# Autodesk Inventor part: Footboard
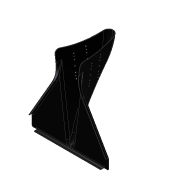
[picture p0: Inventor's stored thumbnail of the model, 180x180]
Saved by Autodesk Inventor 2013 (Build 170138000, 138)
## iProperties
Shininess: 41.0
Length Units: 11269
Angle Units: 11279
Time Units: 11290
Mass Units: 11283
Length Display Precision: 3
Angle Display Precision: 2
Created: 2001-04
Part Number: Footboard
Material: Standard
Document SubType Name: Modellieren
Designer: dl
Density: 1 g/cm^3
Density: 0.0
Volumn: 0.0
Area: 0.0
PropertySet Name: Model Information
Control State: 0
Master: False
Checked Out: False
Author: dl
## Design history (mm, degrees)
sketch "Sketch1"
  geometry: L1 (-28, 0)-(28, 0); L2 (28, 0)-(75, -260); L3 (75, -260)-(-75, -260); L4 (-75, -260)-(-28, 0); L5 (0, 0)-(0, 120.699)
  constraints: 10 end point, 1 equal length, 1 horizontal, 1 midpoint, 1 parallel, 1 perpendicular
  dimensions: "d0" = 150 distance of L2.end L3.end; "d1" = 56 distance of L1.start L1.end; "d2" = 260 vertical distance of L3.end L1.start; "d3" = 47 horizontal distance of L1.start L3.end (derived)
extrude "Extrusion1" new body sketch "Sketch1" distance "d4" = 470; taper "d5" = 0 deg
sketch "Sketch4"
  geometry: L1 (72.458, -470)-(77.542, -470) reference; L2 (150, 0)-(93.206, -455.169) reference; L3 (150, 0)-(0, 0) reference; L4 (0, 0)-(56.794, -455.169) reference; L5 (-146.5, -470)-(296.5, -470); L6 (296.5, -405)-(134.481, -124.375); L7 (-146.5, -405)-(15.519, -124.375); L8 (296.5, -405)-(296.5, -470); L9 (-146.5, -405)-(-146.5, -470); L10 (75, 0)-(75, 36.926)
  constraints: 12 end point, 3 parallel, 2 equal length, 2 point on line, 1 midpoint, 1 perpendicular, 2 other
  dimensions: "d42" = 443 distance of L5.start L5.end; "d43" = 0 distance from line of L5 L1.start; "d44" = 65 distance of L6.start L5.end; "d45" = 30 deg angle of L6 L8; "d46" = 30 deg angle of L7 L9 (= d45); "d47" = 221.5 horizontal distance of L5.end L10.end (derived)
extrude "Extrusion2" join sketch "Sketch4" distance "d48" = 20; taper "d49" = 0 deg
sketch "Sketch6"
  geometry: L1 (324.038, 20)-(357.434, 20); L2 (357.434, 20)-(357.434, 0); L3 (357.434, 0)-(324.038, 0); L4 (324.038, 0)-(324.038, 20); L5 (423.99, 0)-(324.038, 0) reference
  constraints: 8 end point, 2 parallel, 1 horizontal, 1 perpendicular
  dimensions: "d62" = 0 distance from line of L5 L2.end
extrude "Extrusion4" join sketch "Sketch6" distance "d63" = 20; taper "d64" = 0 deg
sketch "Sketch8" dims "d73" = 1000
  geometry: L1 (-260, 0)-(-260, -71.319) reference; L2 (-26.395, 0)-(-260, 0) reference; L3 (-0.319, -2.89)-(-0.319, -19.983); 1 further point
  constraints: 2 end point, 1 perpendicular, 3 other
  dimensions: "d74" = 130 distance from line of L1 point (-130, 480); "d75" = 480 distance from line of L2 point (-130, 480)
extrude "Extrusion6" cut sketch "Sketch8" stored distance "d77" = 300; taper "d78" = 0 deg
sketch "Sketch12"
  geometry: L1 (22, -10)-(-10, -10); L2 (-10, -10)-(-10, 57); L3 (-10, 57)-(22, 57); L4 (22, 57)-(22, -10); L5 (-10, 52.321)-(-10, 0) reference; L6 (0, -10)-(423, -10) reference
  constraints: 8 end point, 2 parallel, 1 horizontal, 1 perpendicular
  dimensions: "d123" = 0 distance from line of L1.end L5; "d124" = 0 distance from line of L6 L1.start; "d125" = 32 distance of L2.end L3.end; "d126" = 67 distance of L3.end L1.start
extrude "Extrusion7" cut sketch "Sketch12" stored distance "d127" = 10; taper "d128" = 0 deg
body "Solid1"
feature "FaceDraft1" dims angle "d17" = 7 deg
sweep "Sweep1" dims "d16" = 0
fillet "Fillet1" dims "d21" = 16.5, "d22" = 32, "d25" = 24, "d26" = 10, "d29" = 23, "d30" = 5, "d34" = 23, "d35" = 7.5, "d38" = 18.5, "d39" = 2.5
fillet "Fillet2" dims "d23" = 32 (= d22), "d24" = 16.5 (= d21), "d27" = 24 (= d25), "d28" = 0, "d31" = 23 (= d29), "d32" = 5, "d36" = 23 (= d34), "d37" = 2.5, "d40" = 18.5 (= d38), "d41" = 7.5
workaxis "Work Axis1"
workaxis "Work Axis2"
workplane "Work Plane1"
sketch "Sketch5"
  geometry: L1 (-118.962, 0)-(-280.981, 0) reference; L2 (-118.962, 0)-(0, 0); L3 (0, 0)-(0, -20); L4 (0, -20)-(-118.962, -20); L5 (-118.962, -20)-(-118.962, 0); L6 (-118.962, -20)-(-280.981, -20) reference
  constraints: 8 end point, 2 parallel, 1 horizontal, 1 perpendicular
  dimensions: "d58" = 0 distance between parallel lines of L6 L4
extrude "Extrusion3" join sketch "Sketch5" stored distance "d56" = 20; taper "d57" = 0 deg
sketch "Sketch7"
  geometry: L1 (-324.038, 20)-(-356.936, 20); L2 (-356.936, 20)-(-356.936, 0); L3 (-356.936, 0)-(-324.038, 0); L4 (-324.038, 0)-(-324.038, 20); L5 (-423.99, 0)-(-324.038, 0) reference
  constraints: 8 end point, 2 parallel, 1 horizontal, 1 perpendicular
  dimensions: "d65" = 0 distance between parallel lines of L5 L3
extrude "Extrusion5" join sketch "Sketch7" distance "d66" = 20; taper "d67" = 0 deg
fillet "Fillet3" dims "d68" = 150
fillet "Fillet4" dims "d69" = 10
fillet "Fillet5" dims "d70" = 10
fillet "Fillet6" dims "d71" = 10
shell "Shell1" dims "d72" = 3
fillet "Fillet7" dims "d79" = 20
sketch "Sketch9"
  geometry: L1 (-36.727, -28.685)-(6.694, -28.685) reference; 3 further points; 1 other entity
  constraints: 1 other
  dimensions: "d80" = 88 distance from line of point (-6.28, 59.315) L1; "d81" = 30 horizontal distance of point (-6.28, 59.315) point (-36.28, -8.366)
hole "Hole1" sketch "Sketch9" diameter "d82" = 6.2; stored, may be unused: countersink angle "d86" = 60 deg, drill point angle "d88" = 118 deg; dims "d83" = 6, "d84" = 4, "d85" = 2, "d87" = 8
pattern_linear "Rectangular Pattern1" dims "d91" = 30
sketch "Sketch10"
  geometry: C1 r 3.1 at (-6.28, 59.315) reference; 1 further point
  dimensions: "d96" = 61 vertical distance of point (-14.28, 120.315) C1.centre; "d97" = 8 horizontal distance of C1.centre point (-14.28, 120.315)
hole "Hole2" sketch "Sketch10" diameter "d98" = 6.2; stored, may be unused: countersink angle "d102" = 60 deg, drill point angle "d104" = 118 deg; dims "d99" = 6, "d100" = 4, "d101" = 2, "d103" = 8
pattern_linear "Rectangular Pattern2" dims "d107" = 30
mirror "Mirror1"
sketch "Sketch11"
  geometry: C1 r 3.1 at (105.72, 120.315) reference; C2 r 3.1 at (75.72, 120.315) reference; C3 r 3.1 at (-14.28, 120.315) reference; C4 r 3.1 at (113.72, 59.315) reference; C5 r 3.1 at (83.72, 59.315) reference; C6 r 3.1 at (-6.28, 59.315) reference; 4 further points
  dimensions: "d108" = 0 vertical distance of C3.centre point (0.72, 120.315); "d109" = 15 distance of C3.centre point (0.72, 120.315); "d110" = 0 vertical distance of C6.centre point (8.72, 59.315); "d111" = 15 distance of C6.centre point (8.72, 59.315) (= d109); "d112" = 0 vertical distance of C1.centre point (90.72, 120.315); "d113" = 0 vertical distance of C4.centre point (98.72, 59.315); "d114" = 15 distance of C2.centre point (90.72, 120.315) (= d109); "d115" = 15 distance of C5.centre point (98.72, 59.315) (= d109)
hole "Hole3" sketch "Sketch11" diameter "d116" = 5; stored, may be unused: countersink angle "d120" = 60 deg, drill point angle "d122" = 118 deg; dims "d117" = 6, "d118" = 4, "d119" = 2, "d121" = 8
mirror "Mirror2"
fillet "Fillet8" dims "d129" = 5
mirror "Mirror3"
workaxis "Work Axis3"
workaxis "Work Axis4"
workplane "Work Plane2"
sketch "Sketch2"
  geometry: L1 (-260, -470)-(0, -470) reference; L2 (0, 0)-(0, -470) reference; L3 (-260, 0)-(-260, -470) reference; L4 (0, 0)-(-260, 0) reference; A1 r 200 centre (-200, 0) between (-46.239, -127.897) and (-0.031, -3.501); A2 r 900 centre (645.685, -703.432) between (-46.239, -127.897) and (-205.431, -410.857); A3 r 100 centre (-300, -378.348) between (-260, -470) and (-205.431, -410.857)
  constraints: 6 point on circle, 3 centre point, 2 tangent
  dimensions: "d6" = 200 radius of A1; "d7" = 100 radius of A3; "d8" = 900 radius of A2; "d9" = 200 distance from line of L2 A1.centre (= d6); "d10" = 40 distance from line of A3.centre L3; "d11" = 0 distance from line of L4 A1.centre
sketch "Sketch3"
  geometry: L1 (-28, 0)-(28, 0) reference; L2 (-75, 500)-(75, 500); L3 (75, 500)-(75, 0); L4 (75, 0)-(-75, 0); L5 (-75, 0)-(-75, 500); 1 further point
  constraints: 8 end point, 2 parallel, 1 horizontal, 1 perpendicular
  dimensions: "d12" = 150 distance of L2.start L2.end; "d13" = 500 distance of L4.end L2.start; "d14" = 0 distance between parallel lines of L1 L4; "d15" = 0 distance from line of point (75, -260) L3
